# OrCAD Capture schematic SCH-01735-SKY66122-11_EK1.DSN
size B; title: SKY66122-11 EK1 EVAL BOARD; rev: A2; note: SCH-01735; note: OTTAWA DESIGN CENTRE; note: 1135 INNOVATION DRIVE
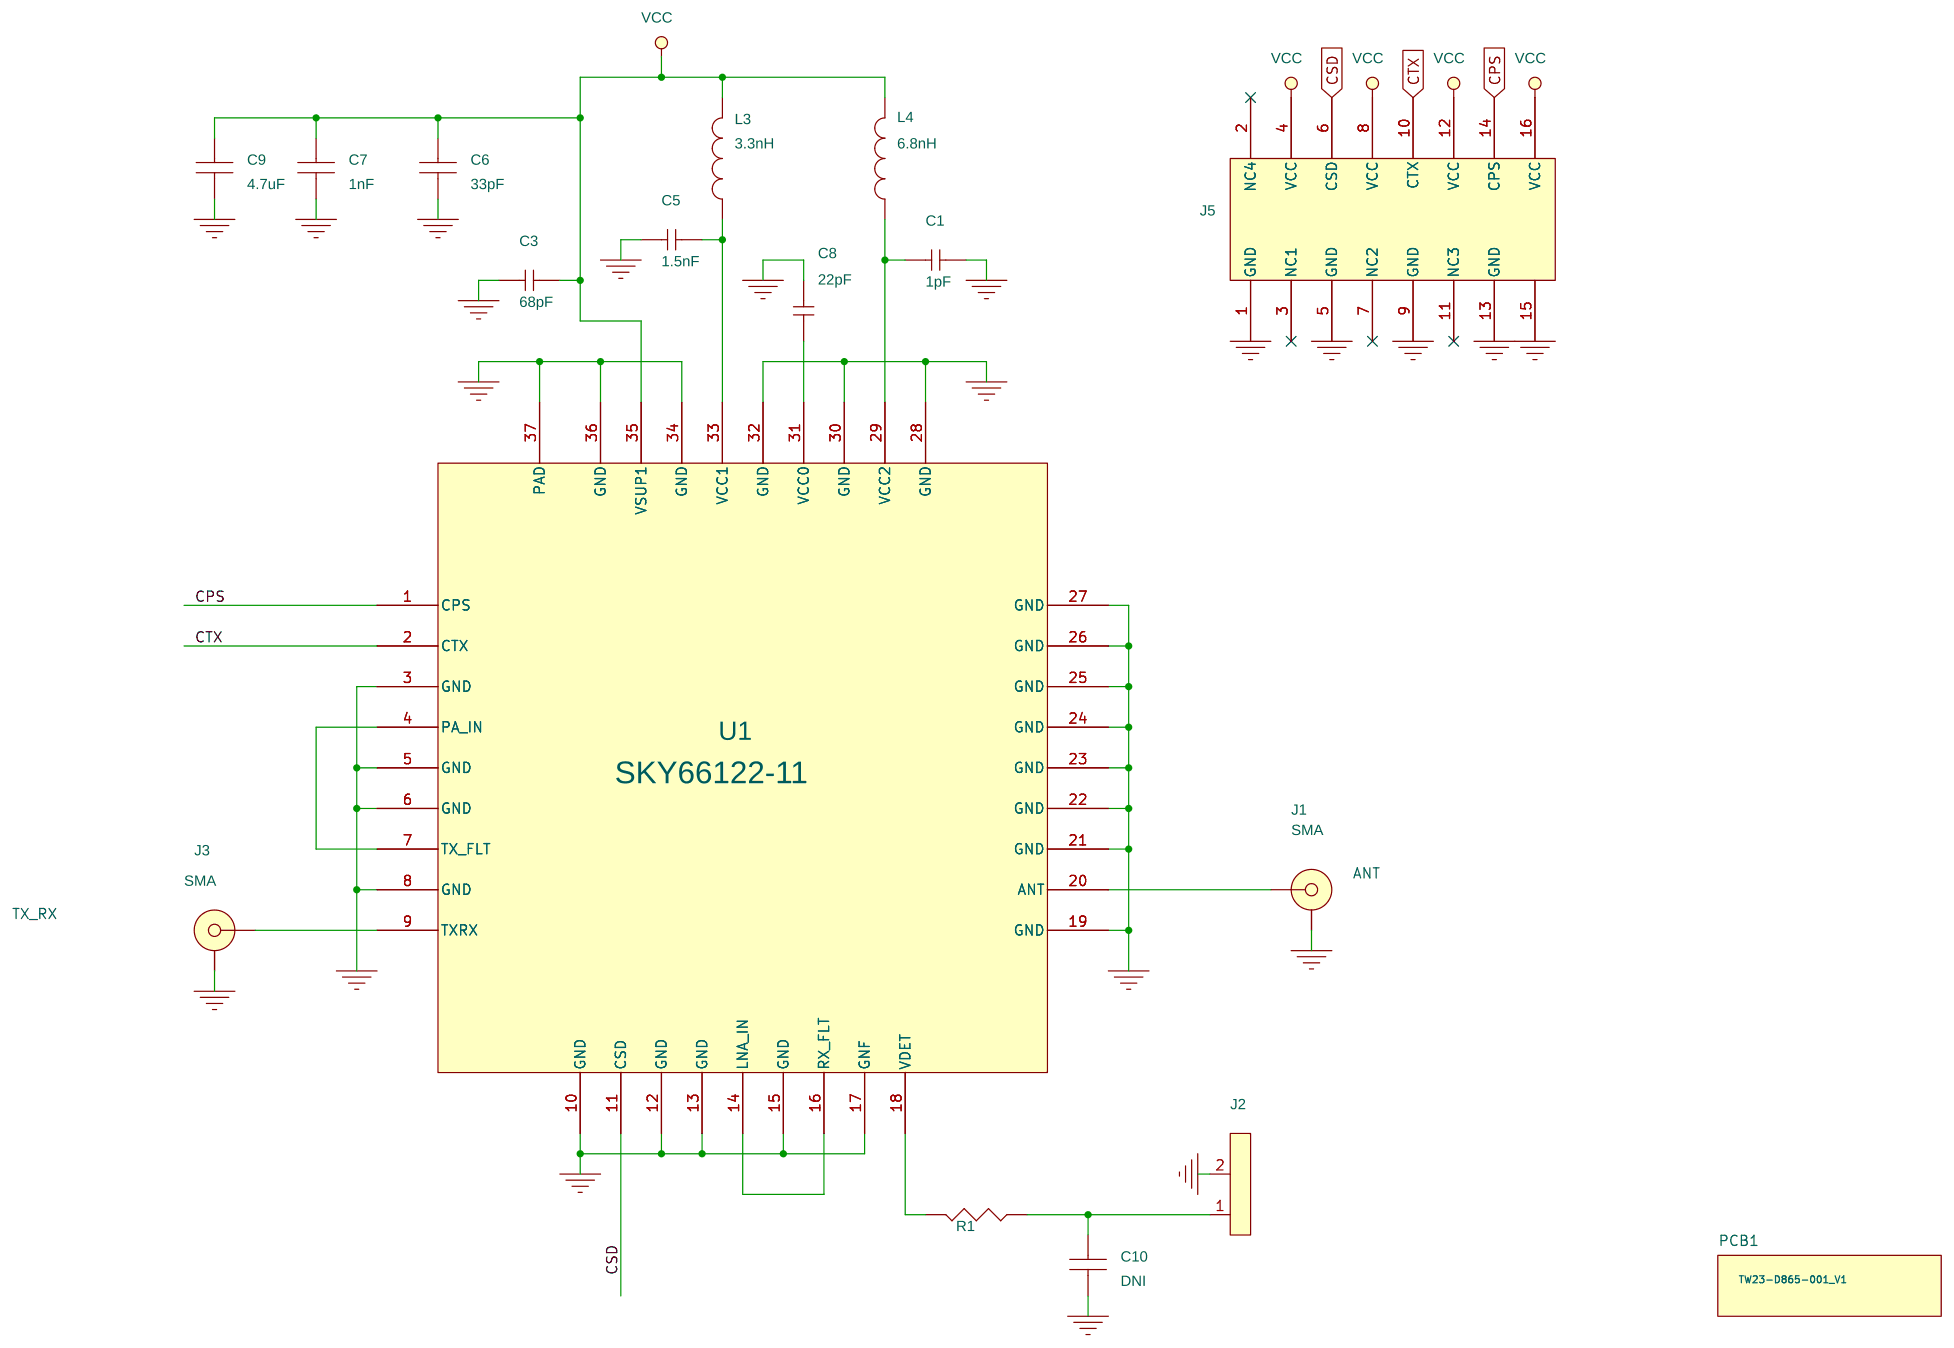
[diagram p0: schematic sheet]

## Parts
C1  1pF  [0201]
C3  68pF  [0201]
C5  1.5nF  [0201]
C6  33pF  [0201]
C7  1nF  [0201]
C8  22pF  [0201]
C9  4.7uF  [0603]
C10  DNI  [0201]
J1  SMA  [SSMA]
J2  HEADER 1X2  [HDR2540P1RST-2]
J3  SMA  [SSMA]
J5  HEADER 8X2  [HDRV2X8_2540P]
L3  3.3nH  [0402]
L4  6.8nH  [0603]
PCB1  TW23-D865-001_V1
R1  0R  [0201]
U1  SKY66122-11  [TBD]

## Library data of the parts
C1 = C: Multilayer Ceramic; MANUFACTURER_PN: GRM0335C1E1R0BD01; Manufacturer: MURATA
C3 = C: Multilayer Ceramic; MANUFACTURER_PN: GRM0335C1E680JD01; Manufacturer: MURATA
C5 = C: Multilayer Ceramic; MANUFACTURER_PN: GRM033R71C152JA01; Manufacturer: MURATA
C6 = CAP_NP: Multilayer Ceramic; CLASS: DISCRETE; MANUFACTURER_PN: GRM0335C1E330JD01; Manufacturer: MURATA; PART_NUMBER: 5406R29-036; VOLTAGE: 50V
C7 = CAP_NP: Multilayer Ceramic; CLASS: DISCRETE; MANUFACTURER_PN: GRM033R71C102JD01; Manufacturer: MURATA; PART_NUMBER: 5406R29-036; VOLTAGE: 50V
C8 = C: Multilayer Ceramic; MANUFACTURER_PN: GRM0335C1E220JD01; Manufacturer: MURATA
C9 = CAP_NP: Multilayer Ceramic; CLASS: DISCRETE; MANUFACTURER_PN: GRM185R61C475KE11; Manufacturer: MURATA; PART_NUMBER: 5406R29-036; VOLTAGE: 50V
C10 = CAP_NP: CLASS: DISCRETE; PART_NUMBER: 5406R29-036; VOLTAGE: 50V
J1 J3 = SMA_3pin: SMA End Launch Straight Jack Receptacle; MANUFACTURER_PN: R19-070-18-0032210MM; Manufacturer: Multicomp; Package: end launch
J2 = Header_7: HEADER 1X2 .100"; MANUFACTURER_PN: TSW-102-07-G-S; Manufacturer: Samtec
J5 = CON16A_0: HEADER 8X2 .100"; MANUFACTURER_PN: TSW-108-07-G-D; Manufacturer: Samtec
L3 = INDUCTOR_SM: wire-wound Inductor; CLASS: DISCRETE; MANUFACTURER_PN: 0402CS-3N3XJL; Manufacturer: Coilcraft; PART_NUMBER: DNI
L4 = INDUCTOR_SM: wire-wound Inductor; CLASS: DISCRETE; MANUFACTURER_PN: 0603CS-6N8XJL; Manufacturer: Coilcraft; PART_NUMBER: DNI
PCB1 = PCB: Manufacturer: Skyworks
R1 = RES_FIXED: RESISTOR; CLASS: DISCRETE; MANUFACTURER_PN: ERJ-1GN0R00C; Manufacturer: Panasonic; PART_NUMBER: 5424R27-134; VOLTAGE: 50V; WATTS: .063W
U1 = SKY66122-11: FRONT-END MODULE; Manufacturer: Skyworks

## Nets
GND: C1.1 C3.2 C5.1 C6.2 C7.2 C8.1 C9.2 C10.2 J1.2(GND_SIGNAL) J1.3(GND_SIGNAL) J2.2 J3.2(GND_SIGNAL) J3.3(GND_SIGNAL) J5.1(GND) J5.5(GND) J5.9(GND) J5.13(GND) J5.15 U1.3(GND) U1.5(GND) U1.6(GND) U1.8(GND) U1.10(GND) U1.12(GND) U1.13(GND) U1.15(GND) U1.17(GNF) U1.19(GND) U1.21(GND) U1.22(GND) U1.23(GND) U1.24(GND) U1.25(GND) U1.26(GND) U1.27(GND) U1.28(GND) U1.30(GND) U1.32(GND) U1.34(GND) U1.36(GND) U1.37(PAD)
VCC: C3.1 C6.1 C7.1 C9.1 J5.4(VCC) J5.8(VCC) J5.12(VCC) J5.16(VCC) L3.2 L4.2 U1.35(VSUP1)
CPS: J5.14(CPS) U1.1(CPS)
CSD: J5.6(CSD) U1.11(CSD)
CTX: J5.10(CTX) U1.2(CTX)
N16701916: C5.2 L3.1 U1.33(VCC1)
N16702208: C1.2 L4.1 U1.29(VCC2)
N16702456: U1.4(PA_IN) U1.7(TX_FLT)
N16702522: J3.1(SIG) U1.9(TXRX)
N16702959: C10.1 J2.1 R1.2
N16702971: U1.14(LNA_IN) U1.16(RX_FLT)
N16703009: R1.1 U1.18(VDET)
N16705117: J1.1(SIG) U1.20(ANT)
N16706234: C8.2 U1.31(VCC0)

Not connected (* = marked no-connect by the designer): J5 2(NC4)* 3(NC1)* 7(NC2)* 11(NC3)*

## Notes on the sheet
- ANT
- TX_RX
